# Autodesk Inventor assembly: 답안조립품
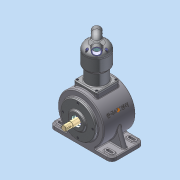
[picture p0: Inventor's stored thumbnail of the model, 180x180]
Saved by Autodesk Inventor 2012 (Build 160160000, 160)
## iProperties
Created: 2015-06
Part Number: 답안조립품
Document SubType Name: Assembly
Designer: Administrator
Author: Administrator
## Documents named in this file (14)
- C:\Users\Administrator\Desktop\450605V1027\답안조립품.iam
- C:\Users\Administrator\Desktop\450605V1027\본체.ipt
- C:\Users\Administrator\Desktop\450605V1027\메인 크랭크 축-구동부.ipt
- C:\Users\Administrator\Desktop\450605V1027\크랭크 서브축.ipt
- C:\Users\Administrator\Desktop\450605V1027\베어링 NA 4902.ipt
- C:\Users\Administrator\Desktop\450605V1027\커넥팅 로드.ipt
- C:\Users\Administrator\Desktop\450605V1027\피스톤.ipt
- C:\Users\Administrator\Desktop\450605V1027\피스톤 핀.ipt
- C:\Users\Administrator\Desktop\450605V1027\실린더.ipt
- C:\Users\Administrator\Desktop\450605V1027\실린더헤드.ipt
- C:\Users\Administrator\Desktop\450605V1027\베어링 6204.ipt
- C:\Users\Administrator\Desktop\450605V1027\메인커버.ipt
- C:\Users\Administrator\Desktop\450605V1027\M4x0.7.ipt
- C:\Users\Administrator\Desktop\450605V1027\M5x0.8.ipt
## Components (14 placed, 4 different names)
1. 피스톤:1
2. 피스톤 핀:1
3. M4x0.7:1
4. M4x0.7:2
5. M4x0.7:3
6. M4x0.7:4
7. M4x0.7:5
8. M4x0.7:6
9. M4x0.7:7
10. M4x0.7:8
11. M5x0.8:1
12. M5x0.8:2
13. M5x0.8:3
14. M5x0.8:4
